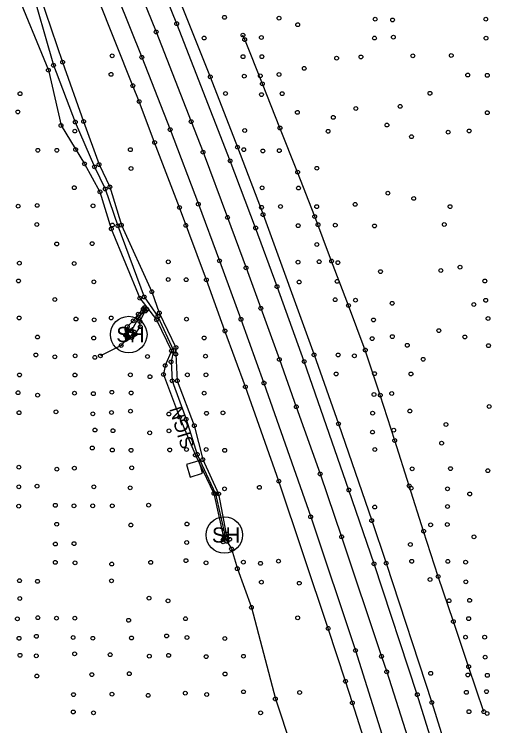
# Model space of a CAD drawing. Extents: x 20503438 to 20508873, y 7964251 to 7984667.
# Drawn here: x 20506193.5 to 20506445, y 7975096.9 to 7975470.8 of the extents above; entities that cross this region are included whole.
import ezdxf

# ---------------------------------------------------------------- set-up
doc = ezdxf.new("R2010")
doc.units = 0
for name, color, linetype in [('SurBreakLine', 7, 'Continuous'), ('SurDrainageArrowDown', 7, 'Continuous'), ('SurDrainageArrowUp', 7, 'Continuous'), ('SurEdgeRoadPaved', 7, 'Continuous'), ('SurEdgeShoulderPaved', 7, 'Continuous'), ('SurNaturalCells', 7, 'Continuous'), ('SurRoadPoints', 7, 'Continuous'), ('SurSurveyPoints', 7, 'Continuous')]:
    doc.layers.add(name, color=color, linetype=linetype)

msp = doc.modelspace()

# ---------------------------------------------------------------- linework, layer by layer
at = {"layer": 'SurBreakLine'}
for points in [[(20506254.12, 7975496.18), (20506268.1, 7975461.5), (20506286.48, 7975414.39), (20506292.75, 7975398.31), (20506305.6, 7975364.06), (20506315.32, 7975337.59), (20506323.1, 7975316.32), (20506332.87, 7975289.39), (20506341.75, 7975264.58), (20506354.3, 7975229.25), (20506365.58, 7975196.27), (20506386.55, 7975133.43), (20506389.28, 7975125.26), (20506400.17, 7975091.1)], [(20506204.02, 7975489.57), (20506218.94, 7975445.66), (20506229.98, 7975414.5), (20506238.08, 7975391.82), (20506243.78, 7975380.06), (20506249.79, 7975360.01), (20506265.78, 7975325), (20506269.72, 7975313.85), (20506278.51, 7975295.7), (20506278.47, 7975292.17), (20506279.19, 7975278.24), (20506288.11, 7975254.67), (20506292.64, 7975236.81), (20506300.9, 7975218.8), (20506304.96, 7975197.71), (20506306.69, 7975194.92)], [(20506193.49, 7975485.46), (20506211.46, 7975441.43), (20506218.08, 7975412.34), (20506230.39, 7975392.2), (20506238.56, 7975377.49), (20506244.49, 7975358.08), (20506259.5, 7975321.6), (20506268.3, 7975310.27), (20506276.12, 7975293.9), (20506272.86, 7975286.21), (20506271.97, 7975281.49), (20506280.33, 7975259.1), (20506288.72, 7975239.15), (20506298.46, 7975219.05), (20506303.7, 7975195.21), (20506303.27, 7975194.67)], [(20506261.97, 7975316.64), (20506261.31, 7975315.93), (20506258.68, 7975313.19), (20506256.04, 7975309.71), (20506252.98, 7975306.78)], [(20506256.18, 7975302.21), (20506257.1, 7975302.73), (20506259.76, 7975306.61), (20506259.58, 7975309.35), (20506262.39, 7975314.88), (20506263.18, 7975315.75)]]:
    msp.add_lwpolyline(points, dxfattribs=at)
for points in [[(20506252.82, 7975304.45), (20506252.04, 7975302.25), (20506253.13, 7975300.69), (20506255.22, 7975300.98), (20506256.18, 7975302.21), (20506256.51, 7975303.84), (20506254.95, 7975304.57), (20506252.76, 7975305.32)], [(20506252.5, 7975302.42), (20506253.42, 7975301.39), (20506253.53, 7975304.58)]]:
    msp.add_lwpolyline(points, close=True, dxfattribs=at)
at = {"layer": 'SurDrainageArrowDown'}
msp.add_lwpolyline([(20506440.28, 7975104.35), (20506432.3, 7975128.04), (20506424.32, 7975151.73), (20506416.34, 7975175.42), (20506408.66, 7975199.21), (20506401.07, 7975223.03), (20506393.47, 7975246.84), (20506385.88, 7975270.66), (20506378.02, 7975294.38), (20506369.15, 7975317.76), (20506360.29, 7975341.13), (20506351.42, 7975364.5), (20506342.43, 7975387.83), (20506333.17, 7975411.05), (20506323.91, 7975434.26), (20506314.65, 7975457.48), (20506313.72, 7975459.79)], dxfattribs=at)
at = {"layer": 'SurDrainageArrowUp'}
for points in [[(20506201.29, 7975488.71), (20506214.15, 7975443.99), (20506225.6, 7975414.16), (20506235.66, 7975390.61), (20506241.33, 7975379.02), (20506247.91, 7975359.64), (20506261.81, 7975322.26), (20506269.05, 7975312.08), (20506277.29, 7975294.07), (20506275.9, 7975288.13), (20506276.47, 7975278.21), (20506283.9, 7975258.08), (20506289.71, 7975239.53), (20506299.25, 7975218.85), (20506304.47, 7975195.73), (20506305.3, 7975193.87), (20506307.7, 7975189.86), (20506310.76, 7975179.49), (20506318.16, 7975159.16), (20506330.76, 7975111.05), (20506339.21, 7975085.68)], [(20506263.03, 7975316.04), (20506261.03, 7975314.52), (20506258.7, 7975310.97), (20506255.1, 7975304.62)], [(20506252.9, 7975300.86), (20506249.69, 7975296.74), (20506238.79, 7975291.29)]]:
    msp.add_lwpolyline(points, dxfattribs=at)
at = {"layer": 'SurEdgeRoadPaved'}
for points in [[(20506532.64, 7974648.96), (20506516.06, 7974719.27), (20506506.62, 7974757.3), (20506498.09, 7974790.71), (20506488.67, 7974827.17), (20506478.91, 7974863.97), (20506468.84, 7974900.69), (20506458.86, 7974936.07), (20506448.53, 7974971.96), (20506417.96, 7975072.9), (20506405.34, 7975113.32), (20506382.6, 7975182.03), (20506369.4, 7975220.83), (20506345.88, 7975288.32), (20506331.62, 7975327.71), (20506320.36, 7975358.51), (20506306.95, 7975393.79), (20506278.91, 7975465.84), (20506257.71, 7975518.12)], [(20506381.79, 7975075.91), (20506371.23, 7975109.03), (20506367.64, 7975120.33), (20506358.51, 7975148.1), (20506332.54, 7975225.5), (20506315, 7975275.08), (20506304.25, 7975304.42), (20506294.47, 7975331.29), (20506280.35, 7975369.28), (20506267.29, 7975403.46), (20506259.14, 7975424.98), (20506255.81, 7975433.25), (20506237.19, 7975479.91)], [(20506247.96, 7975479.81), (20506260.54, 7975448.2), (20506275.43, 7975410.2), (20506290.26, 7975371.02), (20506301.37, 7975341.22), (20506312.67, 7975310.54), (20506324.74, 7975277.04), (20506349.3, 7975206.77), (20506372.83, 7975136.5), (20506386.78, 7975092.48), (20506394.92, 7975066.92), (20506406.39, 7975029.37), (20506415.61, 7974999.14), (20506420.57, 7974982.55), (20506427.17, 7974960.41), (20506437.15, 7974925.73), (20506446.74, 7974891.45), (20506465.93, 7974820.14), (20506474.65, 7974785.33), (20506483.51, 7974751.12), (20506492.4, 7974715.32)]]:
    msp.add_lwpolyline(points, dxfattribs=at)
at = {"layer": 'SurEdgeShoulderPaved'}
msp.add_lwpolyline([(20506267.06, 7975511.74), (20506296.53, 7975437.96), (20506310.81, 7975400.98), (20506324.27, 7975365.52), (20506351.09, 7975291.82), (20506363.94, 7975255.58), (20506381.4, 7975204.73), (20506388.98, 7975182.4), (20506412.98, 7975109.14), (20506424.35, 7975072.59), (20506457.56, 7974962.26), (20506468.15, 7974925.5), (20506488.59, 7974852.02), (20506498.44, 7974814.69), (20506507.99, 7974777.45), (20506517.02, 7974741.08), (20506525.96, 7974704.19)], dxfattribs=at)
at = {"layer": 'SurNaturalCells'}
for centre in [(20506253.69, 7975302.51), (20506303.95, 7975197.19)]:
    msp.add_circle(centre, 9.59, dxfattribs=at)
at = {"layer": 'SurRoadPoints'}
msp.add_lwpolyline([(20506291.51, 7975232.95), (20506291.51, 7975232.95), (20506290.51, 7975236.22), (20506283.96, 7975234.21), (20506285.97, 7975227.66), (20506292.52, 7975229.67), (20506291.51, 7975232.95)], dxfattribs=at)
at = {"layer": 'SurSurveyPoints'}
for centre in [(20506304.01, 7975469.19), (20506332.67, 7975468.73), (20506383.2, 7975468.21), (20506441.33, 7975468.2), (20506278.91, 7975465.84), (20506342.5, 7975465.31), (20506392.35, 7975467.81), (20506268.1, 7975461.5), (20506293.29, 7975458.31), (20506313.72, 7975459.79), (20506314.65, 7975457.48), (20506323.38, 7975458.58), (20506382.84, 7975458.29), (20506392.76, 7975458.79), (20506441.48, 7975458.22), (20506218.94, 7975445.66), (20506244.97, 7975448.96), (20506260.54, 7975448.2), (20506313.76, 7975448.52), (20506323.67, 7975448.52), (20506362.94, 7975447.73), (20506375.71, 7975448.39), (20506403.02, 7975448.93), (20506423.19, 7975449.12), (20506214.15, 7975443.99), (20506345.92, 7975442.38), (20506211.46, 7975441.43), (20506244.39, 7975439.23), (20506314.39, 7975438.26), (20506322.82, 7975438.43), (20506332.69, 7975439.19), (20506431.85, 7975438.87), (20506442.12, 7975438.72), (20506296.53, 7975437.96), (20506255.81, 7975433.25), (20506323.91, 7975434.26), (20506196.55, 7975429.07), (20506304.54, 7975429.18), (20506323.48, 7975428.58), (20506334.33, 7975429.08), (20506412.01, 7975429.28), (20506259.14, 7975424.98), (20506195.39, 7975419.49), (20506373.06, 7975421.29), (20506396.34, 7975422.39), (20506342.3, 7975419.25), (20506361.19, 7975416.61), (20506442.13, 7975419.08), (20506218.08, 7975412.34), (20506225.6, 7975414.16), (20506229.98, 7975414.5), (20506286.48, 7975414.39), (20506389.38, 7975412.58), (20506225.35, 7975409.42), (20506275.43, 7975410.2), (20506314.62, 7975409.73), (20506333.17, 7975411.05), (20506358.46, 7975409.33), (20506421.55, 7975408.89), (20506432.58, 7975409.49), (20506402.33, 7975406.46), (20506267.29, 7975403.46), (20506310.81, 7975400.98), (20506205.93, 7975399.35), (20506215.85, 7975399.35), (20506225.74, 7975399.77), (20506254.56, 7975399.66), (20506292.75, 7975398.31), (20506314.13, 7975399.67), (20506324.16, 7975398.98), (20506332.81, 7975399.16), (20506306.95, 7975393.79), (20506230.39, 7975392.2), (20506235.66, 7975390.61), (20506238.08, 7975391.82), (20506254.89, 7975389.79), (20506352.54, 7975389.9), (20506342.43, 7975387.83), (20506225.05, 7975379.68), (20506241.33, 7975379.02), (20506243.78, 7975380.06), (20506323.77, 7975379.64), (20506342.9, 7975379.49), (20506238.56, 7975377.49), (20506389.9, 7975376.81), (20506290.26, 7975371.02), (20506372.7, 7975370.9), (20506403.48, 7975374.04), (20506195.57, 7975369.98), (20506205.57, 7975370.36), (20506234.91, 7975370.13), (20506280.35, 7975369.28), (20506323.47, 7975369.36), (20506333.46, 7975369.78), (20506352.49, 7975369.72), (20506422.57, 7975369.75), (20506305.6, 7975364.06), (20506324.27, 7975365.52), (20506351.42, 7975364.5), (20506205.34, 7975360.34), (20506245.09, 7975360.03), (20506247.91, 7975359.64), (20506249.79, 7975360.01), (20506283.66, 7975359.86), (20506342.72, 7975359.73), (20506353.17, 7975360.24), (20506362.22, 7975359.98), (20506382.87, 7975359.58), (20506419.54, 7975360.34), (20506244.49, 7975358.08), (20506320.36, 7975358.51), (20506215.82, 7975350.11), (20506234.45, 7975350.3), (20506352.52, 7975349.84), (20506301.37, 7975341.22), (20506360.29, 7975341.13), (20506196.19, 7975340.04), (20506224.99, 7975339.82), (20506274.48, 7975340.7), (20506315.32, 7975337.59), (20506342.66, 7975340.52), (20506353.75, 7975340.78), (20506363.62, 7975340.3), (20506427.81, 7975337.94), (20506386.02, 7975335.57), (20506417.72, 7975336.15), (20506195.71, 7975330.67), (20506235.37, 7975330.21), (20506274.44, 7975331.46), (20506283.84, 7975331.34), (20506294.47, 7975331.29), (20506343.25, 7975330.1), (20506363.22, 7975330.46), (20506440.85, 7975330.65), (20506331.62, 7975327.71), (20506261.81, 7975322.26), (20506265.78, 7975325), (20506214.81, 7975320.94), (20506259.5, 7975321.6), (20506362.2, 7975320.8), (20506372.84, 7975320.55), (20506392.1, 7975318.95), (20506441.3, 7975320.51), (20506261.31, 7975315.93), (20506261.97, 7975316.64), (20506262.39, 7975314.88), (20506263.03, 7975316.04), (20506263.18, 7975315.75), (20506323.1, 7975316.32), (20506369.15, 7975317.76), (20506435.05, 7975318.28), (20506196.06, 7975311.23), (20506244.48, 7975311.22), (20506258.68, 7975313.19), (20506258.7, 7975310.97), (20506261.03, 7975314.52), (20506269.05, 7975312.08), (20506269.72, 7975313.85), (20506442.55, 7975310.95), (20506225.95, 7975310.65), (20506235.52, 7975310.21), (20506256.04, 7975309.71), (20506259.58, 7975309.35), (20506268.3, 7975310.27), (20506284.01, 7975310.58), (20506312.67, 7975310.54), (20506382.35, 7975310.19), (20506252.76, 7975305.32), (20506252.82, 7975304.45), (20506252.98, 7975306.78), (20506253.53, 7975304.58), (20506254.95, 7975304.57), (20506255.1, 7975304.62), (20506256.51, 7975303.84), (20506259.76, 7975306.61), (20506304.25, 7975304.42), (20506416.68, 7975304.59), (20506205.73, 7975301.19), (20506235.28, 7975300.68), (20506252.04, 7975302.25), (20506252.5, 7975302.42), (20506252.9, 7975300.86), (20506253.13, 7975300.69), (20506253.42, 7975301.39), (20506255.22, 7975300.98), (20506256.18, 7975302.21), (20506257.1, 7975302.73), (20506293.31, 7975300.72), (20506381.65, 7975300.38), (20506392.22, 7975301.44), (20506430.35, 7975301.25), (20506249.69, 7975296.74), (20506400.1, 7975296.87), (20506442.77, 7975296.67), (20506276.12, 7975293.9), (20506277.29, 7975294.07), (20506278.51, 7975295.7), (20506378.02, 7975294.38), (20506204.84, 7975291.78), (20506214.8, 7975290.8), (20506225.48, 7975291.32), (20506235.83, 7975290.5), (20506238.79, 7975291.29), (20506263.53, 7975291.01), (20506278.47, 7975292.17), (20506294.06, 7975291.15), (20506332.87, 7975289.39), (20506351.09, 7975291.82), (20506363.77, 7975291.8), (20506372.28, 7975291.32), (20506408.43, 7975289.53), (20506272.86, 7975286.21), (20506275.9, 7975288.13), (20506345.88, 7975288.32), (20506196.23, 7975281.27), (20506225.4, 7975281.23), (20506254.55, 7975281.38), (20506271.97, 7975281.49), (20506284.49, 7975281.37), (20506294.27, 7975281.31), (20506362.7, 7975281.81), (20506382.88, 7975281.96), (20506402, 7975281.81), (20506264.82, 7975280.36), (20506276.47, 7975278.21), (20506279.19, 7975278.24), (20506315, 7975275.08), (20506324.74, 7975277.04), (20506195.5, 7975271.93), (20506205.8, 7975270.63), (20506225.17, 7975271.73), (20506235.08, 7975271.45), (20506244.76, 7975272.2), (20506254.94, 7975271.83), (20506293.3, 7975271.69), (20506382.59, 7975271.02), (20506385.88, 7975270.66), (20506391.9, 7975271.56), (20506341.75, 7975264.58), (20506401.42, 7975262.33), (20506443.11, 7975264.71), (20506196.03, 7975261.43), (20506215.43, 7975261.92), (20506234.78, 7975260.83), (20506244.6, 7975261.56), (20506254.61, 7975262.22), (20506274.74, 7975260.73), (20506280.33, 7975259.1), (20506294.56, 7975261.14), (20506303.18, 7975261.39), (20506381.85, 7975261.21), (20506283.9, 7975258.08), (20506363.94, 7975255.58), (20506420.41, 7975255.24), (20506235.93, 7975252.32), (20506245.39, 7975251.98), (20506274.82, 7975251.91), (20506288.11, 7975254.67), (20506381.81, 7975251.26), (20506392.94, 7975252.29), (20506264.69, 7975250.87), (20506393.47, 7975246.84), (20506418.13, 7975245.44), (20506234.53, 7975242.9), (20506245.06, 7975241.84), (20506254.89, 7975241.72), (20506275.23, 7975241.89), (20506284.04, 7975242.08), (20506294.38, 7975242.12), (20506304.12, 7975241.68), (20506383.06, 7975242.14), (20506288.72, 7975239.15), (20506289.71, 7975239.53), (20506292.64, 7975236.81), (20506195.92, 7975232.81), (20506255.23, 7975232.51), (20506215.85, 7975231.79), (20506225.11, 7975232.32), (20506354.3, 7975229.25), (20506402.68, 7975231.94), (20506422.79, 7975232.05), (20506442.42, 7975230.98), (20506332.54, 7975225.5), (20506195.87, 7975222.49), (20506205.47, 7975222.88), (20506235.36, 7975222.47), (20506254.4, 7975221.94), (20506304.05, 7975221.42), (20506322.33, 7975222.22), (20506401.07, 7975223.03), (20506402.15, 7975221.76), (20506421.22, 7975221.45), (20506298.46, 7975219.05), (20506299.25, 7975218.85), (20506300.9, 7975218.8), (20506369.4, 7975220.83), (20506432.91, 7975218.74), (20506195.86, 7975212.35), (20506215.1, 7975212.8), (20506224.88, 7975212.52), (20506234.75, 7975212.5), (20506245.01, 7975212.48), (20506264.14, 7975212.87), (20506382.96, 7975211.86), (20506421.2, 7975212.14), (20506349.3, 7975206.77), (20506215.82, 7975202.84), (20506284.29, 7975202.93), (20506381.4, 7975204.73), (20506412.36, 7975202.5), (20506421.09, 7975202.7), (20506254.75, 7975202.41), (20506408.66, 7975199.21), (20506303.7, 7975195.21), (20506304.47, 7975195.73), (20506304.96, 7975197.71), (20506365.58, 7975196.27), (20506435.11, 7975196.2), (20506215.11, 7975192.42), (20506224.93, 7975192.66), (20506284.15, 7975193.26), (20506303.23, 7975193.59), (20506303.27, 7975194.67), (20506305.3, 7975193.87), (20506306.69, 7975194.92), (20506401.72, 7975192.19), (20506307.7, 7975189.86), (20506215.06, 7975182.8), (20506225.45, 7975182.53), (20506244.72, 7975181.91), (20506265.24, 7975182.8), (20506283.75, 7975183.72), (20506294.3, 7975182.59), (20506313.92, 7975182.89), (20506322.91, 7975182.3), (20506332.39, 7975183.45), (20506382.6, 7975182.03), (20506388.98, 7975182.4), (20506402.41, 7975183.38), (20506421.36, 7975183.31), (20506430.73, 7975182.9), (20506310.76, 7975179.49), (20506196.27, 7975173.16), (20506205.7, 7975172.84), (20506244.59, 7975173.07), (20506412.04, 7975173.81), (20506416.34, 7975175.42), (20506323.41, 7975172.37), (20506343.3, 7975171.84), (20506430.86, 7975172.57), (20506196.4, 7975163.85), (20506264.35, 7975164), (20506274.32, 7975162.62), (20506422.03, 7975162.64), (20506432.83, 7975162.83), (20506318.16, 7975159.16), (20506195.15, 7975153.12), (20506205.93, 7975153.71), (20506215.71, 7975153.51), (20506225.37, 7975153.47), (20506253.61, 7975152.37), (20506283.51, 7975153.18), (20506342.47, 7975153.69), (20506424.32, 7975151.73), (20506432.34, 7975153.24), (20506358.51, 7975148.1), (20506196.03, 7975142.9), (20506205.15, 7975143.98), (20506224.43, 7975143.32), (20506234.81, 7975142.94), (20506255.15, 7975143.07), (20506273.57, 7975144.15), (20506284.27, 7975143.36), (20506304.21, 7975142.78), (20506430.72, 7975143.49), (20506440.75, 7975143.49), (20506372.83, 7975136.5), (20506196.53, 7975134), (20506205.08, 7975133.69), (20506225.24, 7975134.72), (20506243.9, 7975134.3), (20506264.5, 7975133.55), (20506274.63, 7975133.95), (20506294.4, 7975133.29), (20506313.96, 7975133.48), (20506386.55, 7975133.43), (20506441.04, 7975132.97), (20506432.3, 7975128.04), (20506253.97, 7975124.3), (20506304.29, 7975124.15), (20506389.28, 7975125.26), (20506412.41, 7975124.5), (20506205.39, 7975123.07), (20506234.27, 7975123.82), (20506367.64, 7975120.33), (20506431.87, 7975123.66), (20506442.15, 7975123.45), (20506224.64, 7975113.33), (20506244.86, 7975113.57), (20506263.88, 7975112.9), (20506283.4, 7975114.08), (20506294.67, 7975113.38), (20506314.03, 7975114.82), (20506343.5, 7975114.43), (20506405.34, 7975113.32), (20506431.13, 7975114.52), (20506441.71, 7975114.91), (20506330.76, 7975111.05), (20506412.98, 7975109.14), (20506371.23, 7975109.03), (20506224.52, 7975104.19), (20506235.19, 7975103.77), (20506323, 7975103.71), (20506432.51, 7975104.36), (20506440.28, 7975104.35), (20506442.03, 7975103.36)]:
    msp.add_circle(centre, 1, dxfattribs=at)

# ---------------------------------------------------------------- texts
at = {"layer": 'SurNaturalCells'}
for p in [(20506247.17, 7975298.51), (20506297.43, 7975193.19)]:
    msp.add_text('SH', height=7.995, rotation=360, dxfattribs=at).set_placement(p)
at = {"layer": 'SurRoadPoints'}
msp.add_text('SIGN', height=6.995, rotation=107.094, dxfattribs=at).set_placement((20506288.29, 7975243.68))

doc.saveas('drawing.dxf')
